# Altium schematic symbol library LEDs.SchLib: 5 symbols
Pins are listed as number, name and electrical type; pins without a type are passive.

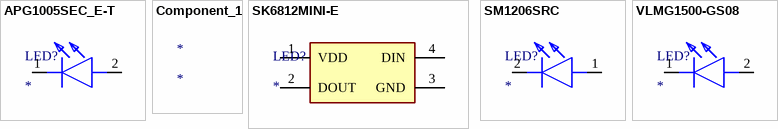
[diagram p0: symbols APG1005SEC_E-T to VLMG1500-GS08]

## APG1005SEC_E-T
designator LED?
LED; Manufacturer_Name: Kingbright; Manufacturer_Part_Number: APG1005SEC/E-T
footprint APG1005SECET
pins: 1 K, 2 A

## Component_1
designator *

## SK6812MINI-E
designator LED?
LED; Manufacturer_Name: Yellow Stone Corp.; Manufacturer_Part_Number: SK6812MINI-E
footprint SK6812MINIE
pins: 1 VDD, 2 DOUT, 3 GND, 4 DIN

## SM1206SRC
designator LED?
RED 1206 1.85 V 20 mA 28 mcd; Manufacturer_Name: Bivar; Manufacturer_Part_Number: SM1206SRC
footprint LEDC3216X120N (Footprint not found)
pins: 1 A, 2 K

## VLMG1500-GS08
designator LED?
LED; Manufacturer_Name: Vishay; Manufacturer_Part_Number: VLMG1500-GS08
footprint LEDC1005X35N
pins: 1 K, 2 A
